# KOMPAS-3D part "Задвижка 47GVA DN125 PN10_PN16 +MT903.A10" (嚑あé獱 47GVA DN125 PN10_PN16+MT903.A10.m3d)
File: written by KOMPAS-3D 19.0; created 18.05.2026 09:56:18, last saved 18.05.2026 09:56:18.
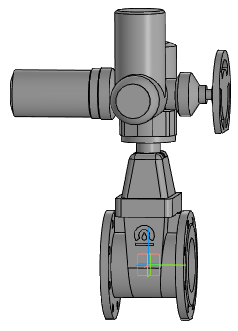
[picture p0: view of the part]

Document properties: Автор: Энергия; Полное имя файла: ..\Задвижка 47GVA DN50_DN1000+MT903.A\Задвижка 47GVA DN125 PN10_PN16+MT903.A10.a3d

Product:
- Part/product: Задвижка 47GVA DN125 PN10_PN16 +MT903.A10
    Масса: 122.438
  - Body: Электропривод МТ903.А10 без блока управления
      Масса: 77.2715
  - Body: Задвижка 47GVA DN125 PN10_PN16 без исполнит. мех.
      Масса: 45.1661

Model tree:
1. Операция без истории:1
2. Операция без истории:2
